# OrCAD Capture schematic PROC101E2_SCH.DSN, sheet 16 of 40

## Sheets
16 39.PERIPHERAL POWER SUPPLY: size C; title: PERIPHERAL POWER SUPPLY
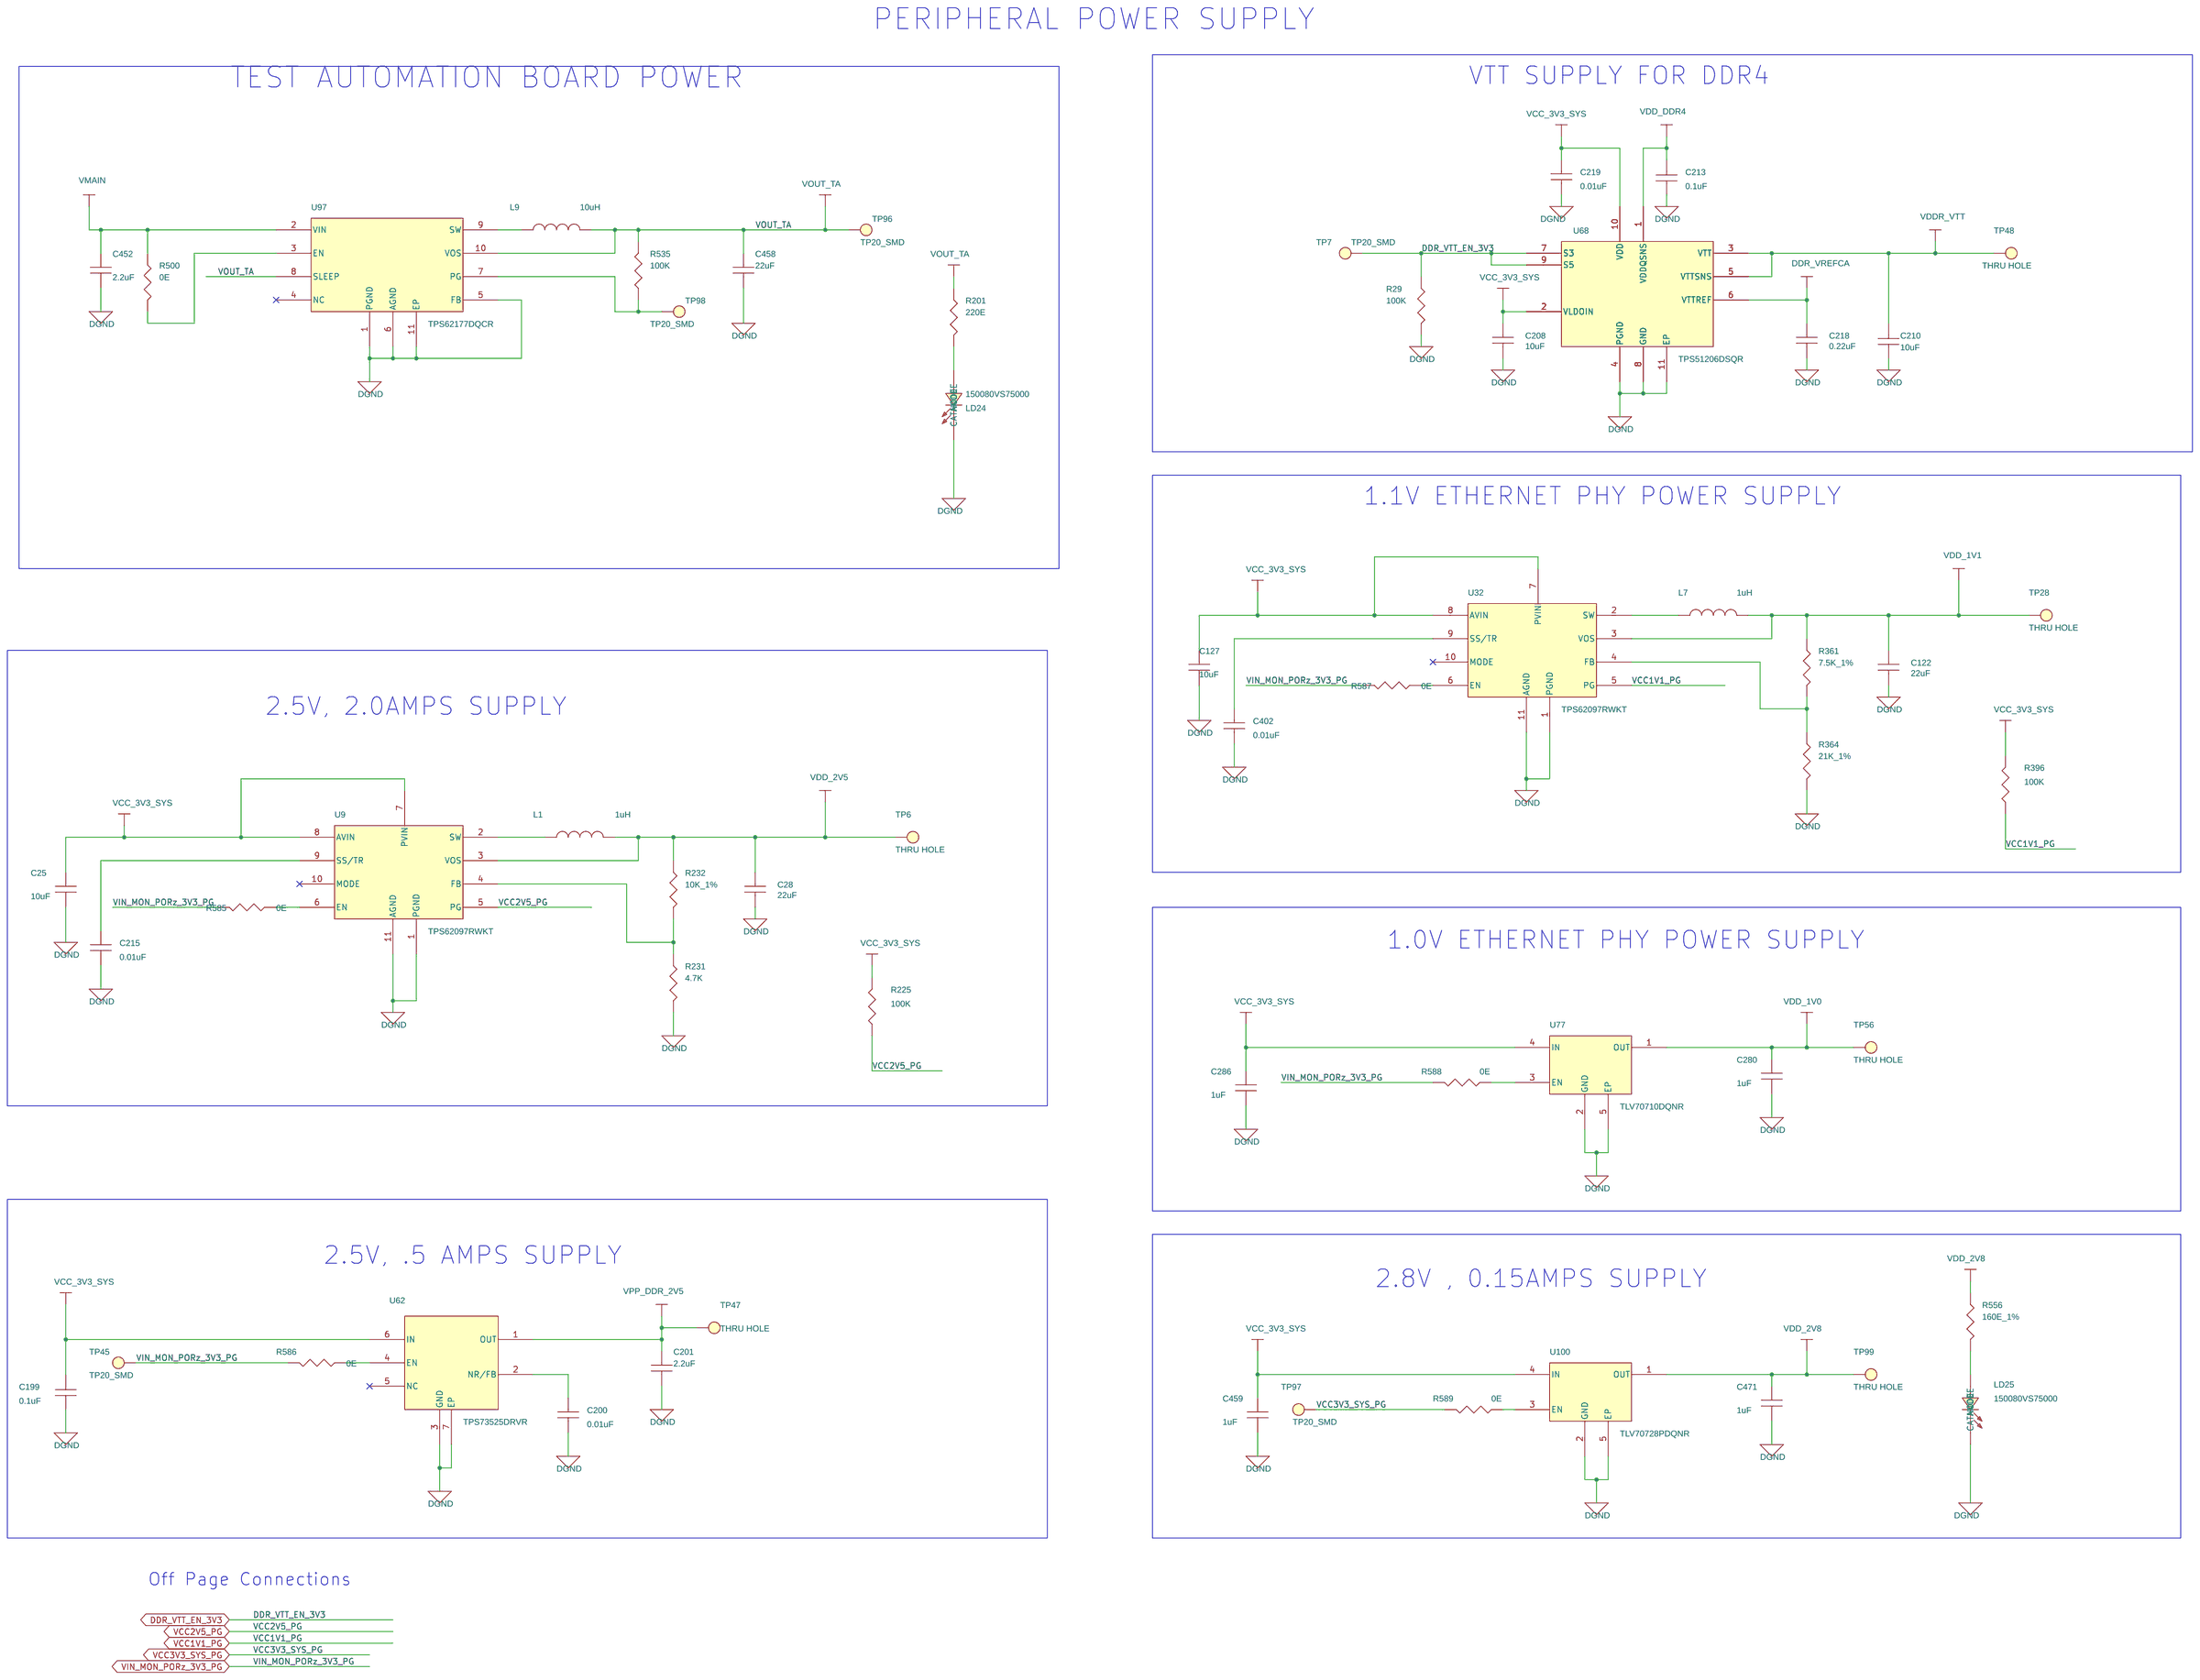
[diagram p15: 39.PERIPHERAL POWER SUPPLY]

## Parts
C25  10uF  [CAP0402_0-75]
C28  22uF  [CAP0603_1]
C122  22uF  [CAP0603_1]
C127  10uF  [CAP0402_0-75]
C199  0.1uF  [CAP0402_0-75]
C200  0.01uF  [CAP0402_0-75]
C201  2.2uF  [CAP0402_0-75]
C208  10uF  [CAP0402_0-75]
C210  10uF  [CAP0402_0-75]
C213  0.1uF  [CAP0402_0-75]
C215  0.01uF  [CAP0402_0-75]
C218  0.22uF  [CAP0201_0-5]
C219  0.01uF  [CAP0402_0-75]
C280  1uF  [CAP0402_0-75]
C286  1uF  [CAP0402_0-75]
C402  0.01uF  [CAP0402_0-75]
C452  2.2uF  [CAP0603_1]
C458  22uF  [CAP0805_1-5]
C459  1uF  [CAP0402_0-75]
C471  1uF  [CAP0402_0-75]
L1  1uH  [IND_744316100_230X220_SMD_4-3]
L7  1uH  [IND_744316100_230X220_SMD_4-3]
L9  10uH  [IND_74438336100_130X130_SMD_2]
LD24  150080VS75000  [LED_150080VS75000_80X50_SMD_0-8]
LD25  150080VS75000  [LED_150080VS75000_80X50_SMD_0-8]
R29  100K  [RES0402_0-5]
R201  220E  [RES0402_0-5]
R225  100K  [RES0402_0-5]
R231  4.7K  [RES0402_0-5]
R232  10K_1%  [RES0402_0-5]
R361  7.5K_1%  [RES0402_0-5]
R364  21K_1%  [RES0402_0-5]
R396  100K  [RES0402_0-5]
R500  0E  [RES0402_0-5]
R535  100K  [RES0402_0-5]
R556  160E_1%  [RES0402_0-5]
R585  0E  [RES0402_0-5]
R586  0E  [RES0402_0-5]
R587  0E  [RES0402_0-5]
R588  0E  [RES0402_0-5]
R589  0E  [RES0402_0-5]
TP6  THRU HOLE  [TP_40X65]
TP7  TP20_SMD  [TP20_SMD]
TP28  THRU HOLE  [TP_40X65]
TP45  TP20_SMD  [TP20_SMD]
TP47  THRU HOLE  [TP_40X65]
TP48  THRU HOLE  [TP_40X65]
TP56  THRU HOLE  [TP_40X65]
TP96  TP20_SMD  [TP20_SMD]
TP97  TP20_SMD  [TP20_SMD]
TP98  TP20_SMD  [TP20_SMD]
TP99  THRU HOLE  [TP_40X65]
U9  TPS62097RWKT  [VQFNHR11_TPS62097_80X80_1]
U32  TPS62097RWKT  [VQFNHR11_TPS62097_80X80_1]
U62  TPS73525DRVR  [SON6_25-59_85X85_0-8]
U68  TPS51206DSQR  [EDFN10_15-74_80X80_0-8]
U77  TLV70710DQNR  [X2SON4_TLV71318P_40X40_0-4]
U97  TPS62177DQCR  [WSON10_19-68_80X120_0-8]
U100  TLV70728PDQNR  [X2SON4_TLV71318P_40X40_0-4]

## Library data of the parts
C25 C127 C208 C210 = CAP: CAP CERAMIC 10uF 10V 20% X5R 0402; Chkd/date: MANIRAJA/300520; Crtd /date: ALVY/260520; Custom_Duty: 15%; Customs_HS_Code: 85322990; Distributor_name: DIGIKEY; Distributor_part_number: 490-GRM155R61A106ME11DTR-ND; Footprint Path: Y:\MIS_DATABASE\Library\ALTIUM_TOOL\PCB_FOOTPRINTS\Altium_Footprint_Lib.PcbLib; Height: 0.55MM; Library Path: Y:\MIS_DATABASE\Library\ALTIUM_TOOL\SCHEMATICS_PARTS\MS_DISCRETE_Library.schlib; Mfr_name: MURATA; Mfr_part_number: GRM155R61A106ME11D; Mistral Part No: 120013110019-R; Package: 0402; Part_type: CAPACITORS\CERAMIC; Project: QCS610_NANOSOM; RoHS: RoHS; Temperature: -55°C+85°C; Tolerance: 20%; Voltage: 10V; Wattage: NA; Weight: 3.1mg; Datasheet: Y:\MIS_DATABASE\DATASHEETS\CAPACITORS\MURATA-GXX-SER_NOV17.PDF
C28 C122 = CAP: CAP CERAMIC 22uF 6.3V 20% X5R 0603; Chkd/date: JEBRAN/090915; Crtd /date: JEBRAN/090915; Custom_Duty: 15%; Customs_HS_Code: 85322990; Distributor_name: DIGIKEY; Distributor_part_number: 490-7611-2-ND; Footprint Path: Y:\MIS_DATABASE\Library\ALTIUM_TOOL\PCB_FOOTPRINTS\Altium_Footprint_Lib.PcbLib; Height: 1.00MM; Library Path: Y:\MIS_DATABASE\Library\ALTIUM_TOOL\SCHEMATICS_PARTS\MS_DISCRETE_Library.schlib; Mfr_name: MURATA; Mfr_part_number: GRM188R60J226MEA0; Mistral Part No: 120015090007-R; Package: 0603; Part_type: CAPACITORS\CERAMIC; Project: OCTBTS_3000; RoHS: RoHS; Temperature: -55°C+85°C; Tolerance: 20%; Voltage: 6.3V; Wattage: NA; Weight: 6.3mg; Datasheet: Y:\MIS_DATABASE\DATASHEETS\CAPACITORS\MURATA-GXX-SER_NOV17.PDF
C199 C213 = CAP: CAP CERAMIC 0.1uF 25V 20% X5R 0402; Alt_Mfr_name: YAGEO AMERICA; Alt_Mfr_part_number: CC0402KRX5R8BB104; Chkd/date: MANIRAJA/170820; Crtd /date: ALVY/170820; Custom_Duty: 15%; Customs_HS_Code: 85322990; Distributor_name: DIGIKEY; Distributor_part_number: 732-7495-1-ND; Footprint Path: Y:\MIS_DATABASE\Library\ALTIUM_TOOL\PCB_FOOTPRINTS\Altium_Footprint_Lib.PcbLib; Height: 0.55MM; Library Path: Y:\MIS_DATABASE\Library\ALTIUM_TOOL\SCHEMATICS_PARTS\MS_DISCRETE_Library.schlib; Mfr_name: WURTH ELECTRONICS; Mfr_part_number: 885012105018; Mistral Part No: 120020080003-R; Package: 0402; Part_type: CAPACITORS\CERAMIC; Project: AM64x_EVM_BRD; RoHS: RoHS; Temperature: -55°C+85°C; Tolerance: 20%; Voltage: 25V; Wattage: NA; Weight: 0.65mg; Datasheet: Y:\MIS_DATABASE\DATASHEETS\CAPACITORS\885012105018.PDF
C200 = CAP: CAP CERAMIC 0.01uF 25V 10% X7R 0402; Assembly: DNI; Chkd/date: MANIRAJA/170820; Crtd /date: ALVY/170820; Custom_Duty: 15%; Customs_HS_Code: 85322990; Distributor_name: DIGIKEY; Distributor_part_number: 732-7545-1-ND; Footprint Path: Y:\MIS_DATABASE\Library\ALTIUM_TOOL\PCB_FOOTPRINTS\Altium_Footprint_Lib.PcbLib; Height: 0.55MM; Library Path: Y:\MIS_DATABASE\Library\ALTIUM_TOOL\SCHEMATICS_PARTS\MS_DISCRETE_Library.schlib; Mfr_name: WURTH ELECTRONICS; Mfr_part_number: 885012205050; Mistral Part No: 120011090040-R; Package: 0402; Part_type: CAPACITORS\CERAMIC; Project: AM64x_EVM_BRD; RoHS: RoHS; Temperature: -55°C+125°C; Tolerance: 10%; Voltage: 25V; Wattage: NA; Weight: 0.65mg; Datasheet: Y:\MIS_DATABASE\DATASHEETS\CAPACITORS\885012205050.PDF
C201 = CAP: CAP CERAMIC 2.2uF 10V 20% X5R 0402; Chkd/date: MANIRAJA/170820; Crtd /date: ALVY/170820; Custom_Duty: 15%; Customs_HS_Code: 85322990; Distributor_name: DIGIKEY; Distributor_part_number: 732-7490-1-ND; Footprint Path: Y:\MIS_DATABASE\Library\ALTIUM_TOOL\PCB_FOOTPRINTS\Altium_Footprint_Lib.PcbLib; Height: 0.55MM; Library Path: Y:\MIS_DATABASE\Library\ALTIUM_TOOL\SCHEMATICS_PARTS\MS_DISCRETE_Library.schlib; Mfr_name: WURTH ELECTRONICS; Mfr_part_number: 885012105013; Mistral Part No: 120019040036-R; Package: 0402; Part_type: CAPACITORS\CERAMIC; Project: AM64x_EVM_BRD; RoHS: RoHS; Temperature: -55°C+85°C; Tolerance: 20%; Voltage: 10V; Wattage: NA; Weight: 0.65mg; Datasheet: Y:\MIS_DATABASE\DATASHEETS\CAPACITORS\885012105013.PDF
C215 C219 C402 = CAP: CAP CERAMIC 0.01uF 25V 10% X7R 0402; Chkd/date: MANIRAJA/170820; Crtd /date: ALVY/170820; Custom_Duty: 15%; Customs_HS_Code: 85322990; Distributor_name: DIGIKEY; Distributor_part_number: 732-7545-1-ND; Footprint Path: Y:\MIS_DATABASE\Library\ALTIUM_TOOL\PCB_FOOTPRINTS\Altium_Footprint_Lib.PcbLib; Height: 0.55MM; Library Path: Y:\MIS_DATABASE\Library\ALTIUM_TOOL\SCHEMATICS_PARTS\MS_DISCRETE_Library.schlib; Mfr_name: WURTH ELECTRONICS; Mfr_part_number: 885012205050; Mistral Part No: 120011090040-R; Package: 0402; Part_type: CAPACITORS\CERAMIC; Project: AM64x_EVM_BRD; RoHS: RoHS; Temperature: -55°C+125°C; Tolerance: 10%; Voltage: 25V; Wattage: NA; Weight: 0.65mg; Datasheet: Y:\MIS_DATABASE\DATASHEETS\CAPACITORS\885012205050.PDF
C218 = CAP: CAP CERAMIC 0.22uF 6.3V 10% X6S AUTO 0201; Chkd/date: MANIRAJA/220219; Crtd /date: ALVY/220219; Custom_Duty: 15%; Customs_HS_Code: 85322990; Distributor_name: DIGIKEY; Distributor_part_number: 490-12230-1-ND; Footprint Path: Y:\MIS_DATABASE\Library\ALTIUM_TOOL\PCB_FOOTPRINTS\Altium_Footprint_Lib.PcbLib; Height: 0.33MM; Library Path: Y:\MIS_DATABASE\Library\ALTIUM_TOOL\SCHEMATICS_PARTS\MS_DISCRETE_Library.schlib; Mfr_name: MURATA; Mfr_part_number: GRT033C80J224KE01D; Mistral Part No: 120019020011-R; Package: 0201; Part_type: CAPACITORS\CERAMIC; Project: TI_J7ES_EVM_SOM; RoHS: RoHS; Temperature: -55°C+105°C; Tolerance: 10%; Voltage: 6.3V; Wattage: NA; Weight: 0.17mg; Datasheet: Y:\MIS_DATABASE\DATASHEETS\CAPACITORS\MURATA-GCM-SER.PDF
C280 C286 C459 C471 = CAP: CAP CERAMIC 1uF 10V 20% X5R 0402; Chkd/date: MANIRAJA/210820; Crtd /date: ALVY/190820; Custom_Duty: 15%; Customs_HS_Code: 85322990; Distributor_name: DIGIKEY; Distributor_part_number: 732-7489-1-ND; Footprint Path: Y:\MIS_DATABASE\Library\ALTIUM_TOOL\PCB_FOOTPRINTS\Altium_Footprint_Lib.PcbLib; Height: 0.55MM; Library Path: Y:\MIS_DATABASE\Library\ALTIUM_TOOL\SCHEMATICS_PARTS\MS_DISCRETE_Library.schlib; Mfr_name: WURTH ELECTRONICS; Mfr_part_number: 885012105012; Mistral Part No: 120020080009-R; Package: 0402; Part_type: CAPACITORS\CERAMIC; Project: AM64x_EVM_BRD; RoHS: RoHS; Temperature: -55°C+85°C; Tolerance: 20%; Voltage: 10V; Wattage: NA; Weight: 0.65mg; Datasheet: Y:\MIS_DATABASE\DATASHEETS\CAPACITORS\885012105012.PDF
C452 = CAP: CAP CERAMIC 2.2uF 35V 10% X5R 0603; Chkd/date: VASANTHA/270117; Crtd /date: MANIRAJA/270117; Custom_Duty: 15%; Customs_HS_Code: 85322990; Distributor_name: DIGIKEY; Distributor_part_number: 490-7204-1-ND; Footprint Path: Y:\MIS_DATABASE\Library\ALTIUM_TOOL\PCB_FOOTPRINTS\Altium_Footprint_Lib.PcbLib; Height: 0.90MM; Library Path: Y:\MIS_DATABASE\Library\ALTIUM_TOOL\SCHEMATICS_PARTS\MS_DISCRETE_Library.schlib; Mfr_name: MURATA; Mfr_part_number: GRM188R6YA225KA12D; Mistral Part No: 120017010016-R; Package: 0603; Part_type: CAPACITORS\CERAMIC; Project: SD820_NANO_SOM; RoHS: RoHS; Temperature: -55°C+85°C; Tolerance: 10%; Voltage: 35V; Wattage: NA; Weight: 6.3mg; Datasheet: Y:\MIS_DATABASE\DATASHEETS\CAPACITORS\MURATA-GXX-SER_NOV17.PDF
C458 = CAP: CAP CERAMIC 22uF 10V 20% X5R 0805; Chkd/date: MANIRAJA/210820; Crtd /date: ALVY/190820; Custom_Duty: 15%; Customs_HS_Code: 85322990; Distributor_name: DIGIKEY; Distributor_part_number: 732-7621-1-ND; Footprint Path: Y:\MIS_DATABASE\Library\ALTIUM_TOOL\PCB_FOOTPRINTS\Altium_Footprint_Lib.PcbLib; Height: 1.45MM; Library Path: Y:\MIS_DATABASE\Library\ALTIUM_TOOL\SCHEMATICS_PARTS\MS_DISCRETE_Library.schlib; Mfr_name: WURTH ELECTRONICS; Mfr_part_number: 885012107011; Mistral Part No: 120020080010-R; Package: 0805; Part_type: CAPACITORS\CERAMIC; Project: AM64x_EVM_BRD; RoHS: RoHS; Temperature: -55°C+85°C; Tolerance: 20%; Voltage: 10V; Wattage: NA; Weight: 5.5mg; Datasheet: Y:\MIS_DATABASE\DATASHEETS\CAPACITORS\885012107011.PDF
L1 L7 = INDUCTOR: IND HI-CURRENT 1uH 11.5A 20% SMD; Chkd/date: MANIRAJA/280520; Crtd /date: ALVY/280520; Custom_Duty: 24%; Customs_HS_Code: 85437099; Distributor_name: DIGIKEY; Distributor_part_number: 732-6176-1-ND; Footprint Path: Y:\MIS_DATABASE\Library\ALTIUM_TOOL\PCB_FOOTPRINTS\Altium_Footprint_Lib.PcbLib; Height: 4.30MM; Library Path: Y:\MIS_DATABASE\Library\ALTIUM_TOOL\SCHEMATICS_PARTS\MS_DISCRETE_Library.schlib; Mfr_name: WURTH ELECTRONICS; Mfr_part_number: 744316100; Mistral Part No: 130020050041-R; Package: SMD; Project: AM64x-GP_EVM BRD; RoHS: RoHS; Temperature: -40°C+150°C; Tolerance: 20%; Voltage: NA; Wattage: NA; Weight: 570mg; Datasheet: Y:\MIS_DATABASE\DATASHEETS\DISCRETES\INDUCTORS\744316100.PDF
L9 = INDUCTOR: IND POWER 10uH 1.2A 20% SMD; Chkd/date: MANIRAJA/180917; Crtd /date: MANIRAJA/180917; Custom_Duty: 24%; Customs_HS_Code: 85369090; Distributor_name: DIGIKEY; Distributor_part_number: 732-5700-1-ND; Height: 2.00MM; Mfr_name: WURTH ELECTRONICS INC; Mfr_part_number: 74438336100; Mistral Part No: 130017090020-R; Package: SMD; Project: P4_RADAR_DI; RoHS: RoHS; Temperature: -40°C+125°C; Tolerance: 20%; Voltage: NA; Wattage: NA; Weight: NA; Datasheet: Y:\MIS_DATABASE\DATASHEETS\DISCRETES\INDUCTORS\74438336100.PDF
LD24 LD25 = DIODE_LED: DIODE LED BRIGHT GREEN SMD; Chkd/date: MANIRAJA/180820; Crtd /date: ALVY/180820; Custom_Duty: 24%; Customs_HS_Code: 85439000; Distributor_name: DIGIKEY; Distributor_part_number: 732-4986-1-ND; Footprint Path: Y:\MIS_DATABASE\Library\ALTIUM_TOOL\PCB_FOOTPRINTS\Altium_Footprint_Lib.PcbLib; Height: 0.80MM; Library Path: Y:\MIS_DATABASE\Library\ALTIUM_TOOL\SCHEMATICS_PARTS\MS_OPTO_Library.schlib; Mfr_name: WURTH ELECTRONICS; Mistral Part No: 130020080012-R; Package: SMD; Part_type: OPTO\LED; Project: AM64x_EVM_BRD; RoHS: RoHS; Temperature: -40°C+85°C; Tolerance: NA; Voltage: NA; Wattage: NA; Weight: 10mg; Datasheet: Y:\MIS_DATABASE\DATASHEETS\DISCRETES\LEDS\150080VS75000.PDF
R29 R225 R396 R535 = RESISTOR: RES 100K 1/16W 5% 0402; Chkd/date: VASANTHA/061216; Crtd /date: BAVISH/010611; Custom_Duty: 15%; Customs_HS_Code: 85332119; Distributor_name: DIGIKEY; Distributor_part_number: 541-100KJCT-ND; Footprint Path: Y:\MIS_DATABASE\Library\ALTIUM_TOOL\PCB_FOOTPRINTS\Altium_Footprint_Lib.PcbLib; Height: 0.40MM; Library Path: Y:\MIS_DATABASE\Library\ALTIUM_TOOL\SCHEMATICS_PARTS\MS_DISCRETE_Library.schlib; Mfr_name: VISHAY; Mfr_part_number: CRCW0402100KJNED; Mistral Part No: 110011060002-R; Package: 0402; Part_type: RESISTORS\FIXED; Project: AM4515_EVM_LCD; RoHS: RoHS; Temperature: -55°C+155°C; Tolerance: 5%; Voltage: NA; Wattage: 1/16W; Weight: 0.65mg; Datasheet: Y:\MIS_DATABASE\DATASHEETS\RESISTORS\CRCW0603.PDF
R201 = RESISTOR: RES 220E 1/10W 5% 0402; Chkd/date: VASANTHA/291216; Crtd /date: GEETHA/260406; Custom_Duty: 15%; Customs_HS_Code: 85332119; Distributor_name: DIGIKEY; Distributor_part_number: P220JCT-ND; Footprint Path: Y:\MIS_DATABASE\Library\ALTIUM_TOOL\PCB_FOOTPRINTS\Altium_Footprint_Lib.PcbLib; Height: 0.40MM; Library Path: Y:\MIS_DATABASE\Library\ALTIUM_TOOL\SCHEMATICS_PARTS\MS_DISCRETE_Library.schlib; Mfr_name: PANASONIC-ECG; Mfr_part_number: ERJ-2GEJ221X; Mistral Part No: 110009030506-R; Package: 0402; Part_type: RESISTORS\FIXED; Project: RED EYE; RoHS: RoHS; Temperature: -55°C+155°C; Tolerance: 5%; Voltage: NA; Wattage: 1/10W; Weight: 0.8mg; Datasheet: Y:\MIS_DATABASE\DATASHEETS\RESISTORS\PAN-ERJSER_NOV17.PDF
R231 = RESISTOR: RES 4.7K 1/16W 5% 0402; Chkd/date: VASANTHA/130516; Crtd /date: VASANTHA/130516; Custom_Duty: 15%; Customs_HS_Code: 85332119; Distributor_name: DIGIKEY; Distributor_part_number: 311-4.7KJRCT-ND; Footprint Path: Y:\MIS_DATABASE\Library\ALTIUM_TOOL\PCB_FOOTPRINTS\Altium_Footprint_Lib.PcbLib; Height: 0.40MM; Library Path: Y:\MIS_DATABASE\Library\ALTIUM_TOOL\SCHEMATICS_PARTS\MS_DISCRETE_Library.schlib; Mfr_name: YAGEO AMERICA; Mfr_part_number: RC0402JR-074K7L; Mistral Part No: 110011060001-R; Package: 0402; Part_type: RESISTORS\FIXED; Project: TMDXCSK368; RoHS: RoHS; Temperature: -55°C+155°C; Tolerance: 5%; Voltage: NA; Wattage: 1/16W; Weight: 0.65mg; Datasheet: Y:\MIS_DATABASE\DATASHEETS\RESISTORS\RCXXXXL-SER_MAR18.PDF
R232 = RESISTOR: RES 10K 1/16W 1% 0402; Chkd/date: VASANTHA/201216; Crtd /date: GEETHA/290506; Custom_Duty: 15%; Customs_HS_Code: 85332119; Distributor_name: DIGIKEY; Distributor_part_number: 311-10.0KLRTR-ND; Footprint Path: Y:\MIS_DATABASE\Library\ALTIUM_TOOL\PCB_FOOTPRINTS\Altium_Footprint_Lib.PcbLib; Height: 0.40MM; Library Path: Y:\MIS_DATABASE\Library\ALTIUM_TOOL\SCHEMATICS_PARTS\MS_DISCRETE_Library.schlib; Mfr_name: YAGEO AMERICA; Mfr_part_number: RC0402FR-0710KL; Mistral Part No: 110015090015-R; Package: 0402; Part_type: RESISTORS\FIXED; Project: VOCERA; RoHS: RoHS; Temperature: -55°C+155°C; Tolerance: 1%; Voltage: NA; Wattage: 1/16W; Weight: 0.65mg; Datasheet: Y:\MIS_DATABASE\DATASHEETS\RESISTORS\RCXXXXL-SER_MAR18.PDF
R361 = RESISTOR: RES 7.5K 1/16W 1% 0402; Chkd/date: MANIRAJA/060619; Crtd /date: ALVY/040619; Custom_Duty: 15%; Customs_HS_Code: 85332119; Distributor_name: DIGIKEY; Distributor_part_number: 541-7.50KLCT-ND; Footprint Path: Y:\MIS_DATABASE\Library\ALTIUM_TOOL\PCB_FOOTPRINTS\Altium_Footprint_Lib.PcbLib; Height: 0.40MM; Library Path: Y:\MIS_DATABASE\Library\ALTIUM_TOOL\SCHEMATICS_PARTS\MS_DISCRETE_Library.schlib; Mfr_name: VISHAY; Mfr_part_number: CRCW04027K50FKED; Mistral Part No: 110019060009-R; Package: 0402; Part_type: RESISTORS\FIXED; Project: MYTHIC_FORMFACTOR_BRD; RoHS: RoHS; Temperature: -55°C+155°C; Tolerance: 1%; Voltage: NA; Wattage: 1/16W; Weight: 0.65mg; Datasheet: Y:\MIS_DATABASE\DATASHEETS\RESISTORS\CRCW0603.PDF
R364 = RESISTOR: RES 21K 1/16W 1% 0402; Chkd/date: MANIRAJA/200319; Crtd /date: MANIRAJA/200319; Custom_Duty: 15%; Customs_HS_Code: 85332119; Distributor_name: DIGIKEY; Distributor_part_number: 311-21.0KLRCT-ND; Footprint Path: Y:\MIS_DATABASE\Library\ALTIUM_TOOL\PCB_FOOTPRINTS\Altium_Footprint_Lib.PcbLib; Height: 0.40MM; Library Path: Y:\MIS_DATABASE\Library\ALTIUM_TOOL\SCHEMATICS_PARTS\MS_DISCRETE_Library.schlib; Mfr_name: YAGEO AMERICA; Mfr_part_number: RC0402FR-0721KL; Mistral Part No: 110015080019-R; Package: 0402; Part_type: RESISTORS\FIXED; Project: OCTASIC_3000; RoHS: RoHS; Temperature: -55°C+155°C; Tolerance: 1%; Voltage: NA; Wattage: 1/16W; Weight: 0.65mg; Datasheet: Y:\MIS_DATABASE\DATASHEETS\RESISTORS\RCXXXXL-SER_MAR18.PDF
R500 R585-R589 = RESISTOR: RES 0E 1/16W JUMPER 0402; Chkd/date: VASANTHA/201216; Crtd /date: MUDDU/190810; Custom_Duty: 15%; Customs_HS_Code: 85332119; Distributor_name: DIGIKEY; Distributor_part_number: 541-0.0JCT-ND; Footprint Path: Y:\MIS_DATABASE\Library\ALTIUM_TOOL\PCB_FOOTPRINTS\Altium_Footprint_Lib.PcbLib; Height: 0.40MM; Library Path: Y:\MIS_DATABASE\Library\ALTIUM_TOOL\SCHEMATICS_PARTS\MS_DISCRETE_Library.schlib; Mfr_name: VISHAY; Mfr_part_number: CRCW04020000Z0ED; Mistral Part No: 110010080019-R; Package: 0402; Part_type: RESISTORS\FIXED; Project: PB_BUGBASE; RoHS: RoHS; Temperature: -55°C+155°C; Tolerance: NA; Voltage: NA; Wattage: 1/16W; Weight: 0.65mg; Datasheet: Y:\MIS_DATABASE\DATASHEETS\RESISTORS\CRCW0603.PDF
R556 = RESISTOR: RES 160E 1/10W 1% 0402; Chkd/date: VASANTHA/170217; Crtd /date: CHAITHANYA/220512; Custom_Duty: 15%; Customs_HS_Code: 85332119; Distributor_name: DIGIKEY; Distributor_part_number: P160LCT-ND; Footprint Path: Y:\MIS_DATABASE\Library\ALTIUM_TOOL\PCB_FOOTPRINTS\Altium_Footprint_Lib.PcbLib; Height: 0.40MM; Library Path: Y:\MIS_DATABASE\Library\ALTIUM_TOOL\SCHEMATICS_PARTS\MS_DISCRETE_Library.schlib; Mfr_name: PANASONIC-ECG; Mfr_part_number: ERJ-2RKF1600X; Mistral Part No: 110012050018-R; Package: 0402; Part_type: RESISTORS\FIXED; Project: GEN_3-8; RoHS: RoHS; Temperature: -55°C+155°C; Tolerance: 1%; Voltage: NA; Wattage: 1/10W; Weight: 0.8mg; Datasheet: Y:\MIS_DATABASE\DATASHEETS\RESISTORS\PAN-ERJSER_NOV17.PDF
TP6 TP28 TP47 TP48 TP56 TP99 = TESTPOINT: TESTPOINT 1.0MM DRILL PTH; Chkd/date: MAZHAR/271211; Crtd /date: SHREESHAIL/041005; Distributor_name: NA; Distributor_part_number: NA; Height: NA; Mfr_name: LOCAL; Mistral Part No: 130009030938; Package: THRU-HOLE; Project: HSE; Datasheet: NA
TP7 TP45 TP96-TP98 = TESTPOINT: TESTPOINT CIR 20 SMD; Chkd/date: SHREESHAIL/171006; Crtd /date: MAZHAR/171006; Custom_Duty: NA; Customs_HS_Code: NA; Distributor_name: NA; Distributor_part_number: NA; Footprint Path: Y:\MIS_DATABASE\Library\ALTIUM_TOOL\PCB_FOOTPRINTS\Altium_Footprint_Lib.PcbLib; Height: NA; Library Path: Y:\MIS_DATABASE\Library\ALTIUM_TOOL\SCHEMATICS_PARTS\MS_DISCRETE_Library.schlib; MECHANICAL 3D STEP FILE: NA; Mfr_name: LOCAL; Mistral Part No: NA; Package: SMD; Project: BT MODULE_CSRBC04; RoHS: NA; Temperature: NA; Tolerance: NA; Voltage: NA; Wattage: NA; Weight: NA; Datasheet: NA
U9 U32 = TPS62097RWKT_VQFNHR11: IC 2A SYNCHRONOUS STEP DOWN CONVERTER WITH IDCS CONTROL VQFN-HR11; Chkd/date: MANIRAJA/270917; Crtd /date: MANIRAJA/270917; Custom_Duty: 15%; Customs_HS_Code: 85423100; Distributor_name: DIGIKEY; Distributor_part_number: 296-43330-1-ND; Height: 1.00MM; Mfr_name: TEXAS INSTRUMENTS; Mistral Part No: 142017090025-R; Package: VQFN-HR11; Part_type: ICS\POWER\CONVERTER; Project: TI_MAXIE_CPB; RoHS: RoHS; Temperature: -40°C+125°C; Tolerance: NA; Voltage: NA; Wattage: NA; Weight: NA; Datasheet: Y:\MIS_DATABASE\DATASHEETS\ICS\POWER\TPS62097.PDF
U62 = TPS73501DRVR_SON6: IC 500mA LOW DROPOUT HIGH PSRR LINEAR REGULATOR SON6; Chkd/date: MANIRAJA/161117; Crtd /date: MANIRAJA/161117; Custom_Duty: 15%; Customs_HS_Code: 85423100; Distributor_name: DIGIKEY; Distributor_part_number: 296-27480-1-ND; Height: 0.80MM; Mfr_name: TEXAS INSTRUMENTS; Mistral Part No: 142017110007-R; Package: SON6; Part_type: ICS\POWER\VOLTAGE REGULATOR; Project: TI_MAXIE_CPB; RoHS: RoHS; Temperature: -40°C+125°C; Tolerance: NA; Voltage: NA; Wattage: NA; Weight: 9.7mg; Datasheet: Y:\MIS_DATABASE\DATASHEETS\ICS\POWER\TPS735.PDF
U68 = TPS51206DSQR_WSON10: IC SINK/SOURCE DDR TERMINATION REGULATOR WSON10; Chkd/date: MANIRAJA/220917; Crtd /date: MANIRAJA/220917; Custom_Duty: 15%; Customs_HS_Code: 85423100; Distributor_name: DIGIKEY; Distributor_part_number: 296-28767-1-ND; Footprint Path: Y:\MIS_DATABASE\Library\ALTIUM_TOOL\PCB_FOOTPRINTS\Altium_Footprint_Lib.PcbLib; Height: 0.80MM; Library Path: Y:\MIS_DATABASE\Library\ALTIUM_TOOL\SCHEMATICS_PARTS\MS_MISCPOWER_Library.schlib; Mfr_name: TEXAS INSTRUMENTS; Mistral Part No: 142017090016-R; Package: WSON10; Part_type: ICS\POWER\VOLTAGE REGULATOR; Project: TI_MAXIE_CPB; RoHS: RoHS; Temperature: -40°C+85°C; Tolerance: NA; Voltage: NA; Wattage: NA; Weight: NA; Datasheet: Y:\MIS_DATABASE\DATASHEETS\ICS\POWER\TPS51206.PDF
U77 = TLV71318PDQNR_X2SON4: IC 200mA LOW IQ LOW NOISE LDO REGULATOR FOR PORTABLE DEVICE X2SON-4; Chkd/date: MANIRAJA/270520; Crtd /date: ALVY/250520; Custom_Duty: 15%; Customs_HS_Code: 85423100; Distributor_name: DIGIKEY; Distributor_part_number: 296-40623-1-ND; Footprint Path: Y:\MIS_DATABASE\Library\ALTIUM_TOOL\PCB_FOOTPRINTS\Altium_Footprint_Lib.PcbLib; Height: 0.40MM; Library Path: Y:\MIS_DATABASE\Library\ALTIUM_TOOL\SCHEMATICS_PARTS\MS_MISCPOWER_Library.schlib; Mfr_name: TEXAS INSTRUMENTS; Mistral Part No: 142020050029-R; Package: X2SON-4; Part_type: ICS\POWER\VOLTAGE REGULATOR; Project: AM64x-GP_EVM BRD; RoHS: RoHS; Temperature: -40°C+125°C; Tolerance: NA; Voltage: NA; Wattage: NA; Weight: 4.1mg; Datasheet: Y:\MIS_DATABASE\DATASHEETS\ICS\POWER\TLV707X.PDF
U97 = TPS62177_WSON10: IC 3.3V 0.5A STEP DOWN CONVERTER WITH SLEEP MODE WSON10; Chkd/date: MANIRAJA/170719; Crtd /date: MANIRAJA/170719; Custom_Duty: 15%; Customs_HS_Code: 85423100; Distributor_name: DIGIKEY; Distributor_part_number: 296-41856-1-ND; Footprint Path: Y:\MIS_DATABASE\Library\ALTIUM_TOOL\PCB_FOOTPRINTS\Altium_Footprint_Lib.PcbLib; Height: 0.80MM; Library Path: Y:\MIS_DATABASE\Library\ALTIUM_TOOL\SCHEMATICS_PARTS\MS_MISCPOWER_Library.schlib; Mfr_name: TEXAS INSTRUMENTS; Mistral Part No: 142019070007-R; Package: WSON10; Part_type: ICS\POWER\DC-DC CONVERTER; Project: TI_MAXIE_CPB; RoHS: RoHS; Temperature: -40°C+85°C; Tolerance: NA; Voltage: NA; Wattage: NA; Weight: 15mg; Datasheet: Y:\MIS_DATABASE\DATASHEETS\ICS\POWER\TPS62177.PDF
U100 = TLV71318PDQNR_X2SON4: IC 200mA LOW IQ LOW NOISE LDO REGULATOR FOR PORTABLE DEVICE X2SON-4; Chkd/date: MANIRAJA/170420; Crtd /date: ALVY/160420; Custom_Duty: 15%; Customs_HS_Code: 85423100; Distributor_name: DIGIKEY; Distributor_part_number: 296-39289-1-ND; Footprint Path: Y:\MIS_DATABASE\Library\ALTIUM_TOOL\PCB_FOOTPRINTS\Altium_Footprint_Lib.PcbLib; Height: 0.40MM; Library Path: Y:\MIS_DATABASE\Library\ALTIUM_TOOL\SCHEMATICS_PARTS\MS_MISCPOWER_Library.schlib; Mfr_name: TEXAS INSTRUMENTS; Mistral Part No: 142020040017-R; Package: X2SON-4; Part_type: ICS\POWER\VOLTAGE REGULATOR; Project: AM64x-GP_EVM BRD; RoHS: RoHS; Temperature: -40°C+125°C; Tolerance: NA; Voltage: NA; Wattage: NA; Weight: 1.5mg; Datasheet: Y:\MIS_DATABASE\DATASHEETS\ICS\POWER\TLV707X.PDF

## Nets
DGND: C25.2 C28.2 C122.2 C127.2 C199.1 C200.2 C201.2 C208.2 C210.1 C213.1 C215.2 C218.2 C219.2 C280.2 C286.2 C402.2 C452.2 C458.2 C459.2 C471.2 LD24.1(CATHODE) LD25.1(CATHODE) R29.2 R231.2 R364.2 U9.1(PGND) U9.11(AGND) U32.1(PGND) U32.11(AGND) U62.3(GND) U62.7(EP) U68.4(PGND) U68.8(GND) U68.11(EP) U77.2(GND) U77.5(EP) U97.1(PGND) U97.5(FB) U97.6(AGND) U97.11(EP) U100.2(GND) U100.5(EP) ; also on sheet 2 3 4 5 6 7 8 9 10 11 12 13 14 15 17 18 19 20 21 22 23 24 25 26 27 28 29 30 39 40
VCC1V1_PG: R396.1 U32.5(PG) ; also on sheet 8
VCC2V5_PG: R225.1 U9.5(PG) ; also on sheet 8
VCC3V3_SYS_PG: R589.2 TP97.1(TP) ; also on sheet 15 17
VCC3V3_TA: C458.1 L9.2 R201.1 R535.2 TP96.1(TP) U97.8(SLEEP) U97.10(VOS) ; also on sheet 17 29 30
VCC_3V3_SYS: C25.1 C127.1 C199.2 C208.1 C219.1 C286.1 C459.1 R225.2 R396.2 U9.7(PVIN) U9.8(AVIN) U32.7(PVIN) U32.8(AVIN) U62.6(IN) U68.2(VLDOIN) U68.10(VDD) U77.4(IN) U100.4(IN) ; also on sheet 2 5 6 7 8 10 11 12 13 14 15 17 18 19 20 21 23 24 25 26 27 29 30 39 40
VDD_1V0: C280.1 TP56.1(TP) U77.1(OUT) ; also on sheet 2
VDD_1V1: C122.1 L7.2 R361.1 TP28.1(TP) U32.3(VOS) ; also on sheet 39 40
VDD_2V5: C28.1 L1.2 R232.1 TP6.1(TP) U9.3(VOS) ; also on sheet 2 39 40
VDD_2V8: C471.1 R556.1 TP99.1(TP) U100.1(OUT) ; also on sheet 6
VDD_DDR4: C213.2 U68.1(VDDQSNS) ; also on sheet 3 4 14 22
VDDR_VTT: C210.2 TP48.1(TP) U68.3(VTT) U68.5(VTTSNS) ; also on sheet 22
VIN_MON_PORz_3V3_PG: R585.2 R586.2 R587.2 R588.2 TP45.1(TP) ; also on sheet 17 25
DDR_VREFCA: C218.1 U68.6(VTTREF) ; also on sheet 22
DDR_VTT_EN_3V3: R29.1 TP7.1(TP) U68.7(S3) U68.9(S5) ; also on sheet 13
VMAIN: C452.1 R500.1 U97.2(VIN) ; also on sheet 4 5 8 17
VPP_DDR_2V5: C201.1 TP47.1(TP) U62.1(OUT) ; also on sheet 22
N17786037: L1.1 U9.2(SW)
N17786049: R231.1 R232.2 U9.4(FB)
N19031494: C215.1 U9.9(SS/TR)
N20142928: C200.1 U62.2(NR/FB)
N26016842: L9.1 U97.9(SW)
N26016868: R535.1 TP98.1(TP) U97.7(PG)
N26016893: R500.2 U97.3(EN)
N26733190: R361.2 R364.1 U32.4(FB)
N26733205: L7.1 U32.2(SW)
N26733231: C402.1 U32.9(SS/TR)
N27944274: R585.1 U9.6(EN)
N27944496: R586.1 U62.4(EN)
N27944776: R587.1 U32.6(EN)
N27944822: R588.1 U77.3(EN)
N27945052: R589.1 U100.3(EN)
N28118607: LD25.2(ANODE) R556.2
N28118686: LD24.2(ANODE) R201.2

Not connected (* = marked no-connect by the designer): U9 10(MODE)*; U32 10(MODE)*; U62 5(NC)*; U97 4(NC)*

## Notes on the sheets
sheet 16
- PERIPHERAL POWER SUPPLY
- TEST AUTOMATION BOARD POWER
- VTT SUPPLY FOR DDR4
- 1.1V ETHERNET PHY POWER SUPPLY
- 2.5V, 2.0AMPS SUPPLY
- 1.0V ETHERNET PHY POWER SUPPLY
- 2.5V, .5 AMPS SUPPLY
- 2.8V , 0.15AMPS SUPPLY
- Off Page Connections
